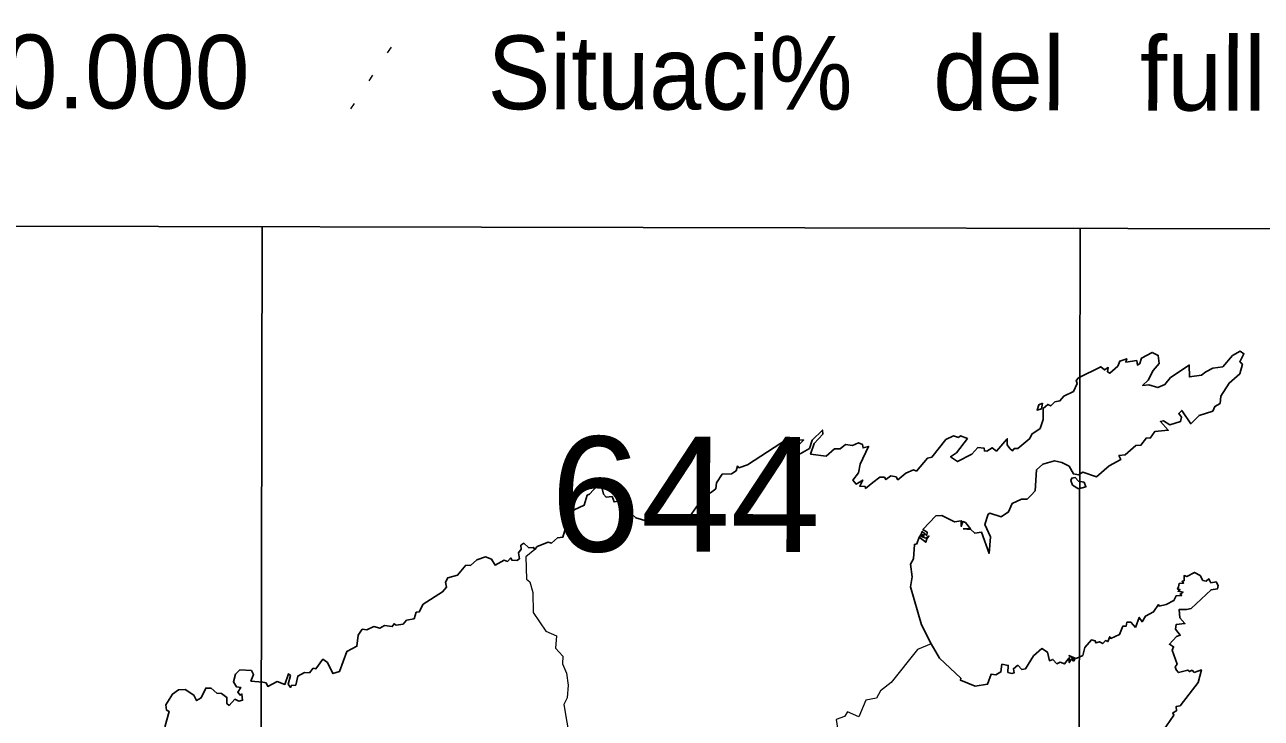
# Model space of a CAD drawing. Extents: x 483843 to 488449, y 4381269 to 4384483.
# Drawn here: x 488069.8 to 488279.3, y 4383527.2 to 4383644.8 of the extents above; entities that cross this region are included whole.
import ezdxf
from ezdxf.enums import TextEntityAlignment as Align

# ---------------------------------------------------------------- set-up
doc = ezdxf.new("R2010")
doc.units = 0
doc.header["$LTSCALE"] = 3.8
doc.linetypes.add('DOTTED', pattern=[1.5, 0.3, -1.2])
for name, color, linetype, lineweight in [('1', 7, 'Continuous', 13), ('2', 7, 'DOTTED', 13), ('3', 7, 'Continuous', 25)]:
    doc.layers.add(name, color=color, linetype=linetype, lineweight=lineweight)

msp = doc.modelspace()

# ---------------------------------------------------------------- linework, layer by layer
at = {"layer": '1', "lineweight": 25}
for p, q in [((487971.5, 4383610.79), (488387.18, 4383609.99)), ((488109.02, 4383068.58), (488110.06, 4383610.53)), ((488247.57, 4383068.31), (488248.62, 4383610.26))]:
    msp.add_line(p, q, dxfattribs=at)
at = {"layer": '2'}
msp.add_line((488125.05, 4383630.5), (488134.4, 4383644.78), dxfattribs=at)
at = {"layer": '3'}
for points in [[(488248.33, 4383584.92), (488252.08, 4383586.8), (488252.73, 4383586.26), (488253.36, 4383586.67), (488253.22, 4383585.97), (488253.64, 4383585.71), (488254.96, 4383586.88), (488255.3, 4383587.73), (488256.49, 4383588.15), (488256.32, 4383587.59), (488258.17, 4383587.86), (488258.29, 4383587.1), (488258.73, 4383587.33), (488259.01, 4383588.27), (488260.77, 4383589.24), (488261.83, 4383588.73), (488261.97, 4383587.35), (488260.97, 4383586.19)], [(488269.87, 4383585.94), (488271.07, 4383586.57), (488272.74, 4383586.78), (488274.41, 4383588.69), (488275.68, 4383589.44), (488276.34, 4383589.02), (488275.62, 4383587.65), (488276.09, 4383587.23), (488275.66, 4383585.62), (488273.81, 4383584.04), (488272.44, 4383581.84), (488272.31, 4383580.58), (488271.42, 4383580.08), (488271.09, 4383579.29)], [(488260.97, 4383586.19), (488260.12, 4383584.51), (488259.16, 4383583.65), (488260.21, 4383583.76), (488261.75, 4383583.26), (488262.96, 4383583.79), (488263.87, 4383584.96), (488267.06, 4383587.08), (488267.11, 4383585.08), (488269.16, 4383585.39), (488269.87, 4383585.94)], [(488248.33, 4383584.92), (488247.9, 4383584.5), (488248.11, 4383583.95), (488247.44, 4383582.61), (488245.82, 4383581.82), (488245.16, 4383581), (488244.33, 4383580.88), (488243.61, 4383580.17), (488243.12, 4383580.42), (488242.33, 4383579.72), (488242.34, 4383577.89), (488241.84, 4383576.35), (488240.41, 4383575.4), (488240.09, 4383574.66), (488238.05, 4383572.95), (488237.44, 4383572.97), (488237.14, 4383572.57), (488236.68, 4383572.96)], [(488271.09, 4383579.29), (488268.73, 4383578.56), (488267.32, 4383577.15), (488265.79, 4383579.41), (488265.29, 4383578.86), (488265.77, 4383578.28), (488265.6, 4383577.5), (488263.76, 4383576.96), (488262.72, 4383577.63), (488262.18, 4383577.52), (488263.51, 4383576.04), (488261.24, 4383575.81), (488260.45, 4383574.72), (488259.81, 4383574.73)], [(488206.98, 4383572.88), (488205.57, 4383571.67), (488202.94, 4383572), (488203.53, 4383573.78), (488205.03, 4383575.38), (488204.93, 4383576.08), (488203.18, 4383574.37), (488202.74, 4383572.95), (488201.17, 4383572.06), (488200.32, 4383572.46), (488200.29, 4383572.94), (488201.74, 4383574.38), (488199.72, 4383574.41)], [(488199.72, 4383574.41), (488199.01, 4383574.59), (488192.23, 4383570.19), (488190.8, 4383569.68), (488190.55, 4383569.97), (488190.3, 4383569.17), (488189.55, 4383568.64), (488187.93, 4383568.57), (488186.98, 4383567.11), (488186.86, 4383566.13), (488186, 4383565.41), (488185.03, 4383565.14)], [(488213.45, 4383567.2), (488212.24, 4383566.18), (488212.16, 4383566.52), (488211.25, 4383566.54), (488211.77, 4383567.6), (488210.63, 4383566.93), (488210.1, 4383567.56), (488211.05, 4383568.83), (488211.31, 4383570.32), (488212.75, 4383573.3), (488211.82, 4383573.05), (488211.73, 4383573.61), (488211.03, 4383573.91), (488210.05, 4383573.47), (488208.87, 4383573.65), (488207.97, 4383572.88), (488206.98, 4383572.88)], [(488228, 4383574.81), (488227.14, 4383575.11), (488225.85, 4383574.5), (488223.48, 4383571.48), (488222.71, 4383571.3), (488220.85, 4383569.12), (488220.39, 4383569.31), (488219.09, 4383568.74), (488217.72, 4383567.64), (488217.42, 4383568.15), (488216.55, 4383568.3), (488215.69, 4383567.69), (488215.43, 4383568.11), (488214.65, 4383568.07), (488213.45, 4383567.2)], [(488236.68, 4383572.96), (488236.23, 4383573.59), (488236.24, 4383574.6), (488234.4, 4383572.51), (488233.68, 4383573.07), (488232.77, 4383572.51), (488232.39, 4383572.54), (488232.34, 4383572.99), (488231.29, 4383573.1), (488230.23, 4383571.99), (488227.79, 4383570.73), (488226.64, 4383571.54), (488227.64, 4383572.19), (488229.5, 4383574.64), (488228.32, 4383575.07), (488228, 4383574.81)], [(488259.81, 4383574.73), (488258.89, 4383573.51), (488258.04, 4383573.45), (488256.23, 4383571.85), (488255.16, 4383571.74), (488255.51, 4383571.1), (488253.51, 4383569.99), (488251.35, 4383568.17), (488249.06, 4383568.96), (488248.32, 4383568.47)], [(488248.32, 4383568.47), (488247.44, 4383568.64), (488246.72, 4383569.94), (488245.49, 4383570.58), (488244.26, 4383570.84), (488242.25, 4383570.32), (488241.21, 4383569.32), (488240.97, 4383565.76), (488240.28, 4383565.06)], [(488248.32, 4383567.43), (488247.74, 4383568.02), (488247.16, 4383567.94), (488247.04, 4383567.53), (488247.3, 4383566.74), (488248.32, 4383566.12)], [(488165.5, 4383565.18), (488166.84, 4383566.66), (488167.61, 4383566.15), (488167.88, 4383565.18)], [(488248.32, 4383567.43), (488249.26, 4383567.24), (488249.57, 4383566.47), (488248.32, 4383566.12)], [(488165.5, 4383565.18), (488165.1, 4383565.02), (488164.6, 4383563.37), (488162.88, 4383562.55), (488161.84, 4383560.78), (488160.96, 4383557.91), (488160.08, 4383557.82), (488159.07, 4383556.93), (488158.47, 4383557.05), (488156.64, 4383556.33), (488156.24, 4383555.85)], [(488167.88, 4383565.18), (488168.3, 4383564.69), (488169.3, 4383564.81), (488169.66, 4383563.89), (488170.72, 4383564.08), (488171.39, 4383563.34), (488172.34, 4383563.58), (488171.94, 4383562.5), (488173.33, 4383561.17), (488175.25, 4383560.63), (488176.34, 4383561.39), (488176.91, 4383561.17), (488177.1, 4383560.55), (488177.52, 4383560.89), (488177.98, 4383560.48), (488179.28, 4383560.83)], [(488185.03, 4383565.14), (488184.83, 4383563.72), (488184.05, 4383563.67), (488181.97, 4383560.75), (488181.15, 4383560.5), (488180.75, 4383560.78), (488180.41, 4383560.33), (488179.28, 4383560.83)], [(488240.28, 4383565.06), (488239.61, 4383564.35), (488238.68, 4383564.37), (488237.06, 4383563.6), (488236.47, 4383562.21), (488235.24, 4383561.34), (488233.29, 4383562), (488232.99, 4383561.8), (488232.43, 4383560.04), (488233.41, 4383557.95), (488233.18, 4383555.16), (488231.9, 4383558.75), (488230.75, 4383558.58), (488230.06, 4383559.2), (488228.75, 4383559.33)], [(488228.75, 4383559.33), (488230.02, 4383559.33), (488229.16, 4383560.42), (488228.74, 4383560.58), (488228.45, 4383559.74), (488228.46, 4383560.71), (488227.3, 4383560.54), (488225.16, 4383561.59), (488224.13, 4383561.52), (488221.96, 4383559.21), (488222.67, 4383558.77), (488222.61, 4383558.23), (488221.85, 4383558.89), (488221.64, 4383558.45), (488222.18, 4383558.26), (488221.54, 4383558.29), (488222.17, 4383557.96), (488221.43, 4383558.13), (488222.47, 4383557.74), (488222.98, 4383558.11), (488222.6, 4383557.63)], [(488222.6, 4383557.63), (488222.44, 4383557.05), (488221.32, 4383557.93), (488220.94, 4383556.8), (488220.53, 4383556.7), (488220.37, 4383554.24), (488219.86, 4383553.35), (488220.16, 4383551.21), (488219.85, 4383549.52), (488221.73, 4383543.04), (488223.37, 4383539.84)], [(488156.24, 4383555.85), (488156, 4383556.17), (488155.22, 4383556.1), (488154.34, 4383556.9), (488153.86, 4383556.54), (488153.93, 4383555.87), (488153.48, 4383555.24), (488153.64, 4383554.26), (488153.17, 4383553.97), (488152.32, 4383554.03), (488152.15, 4383554.4), (488151.61, 4383553.8), (488151.04, 4383554), (488149.48, 4383553.18), (488148.91, 4383554.2), (488147.84, 4383554.56), (488146.39, 4383554.07), (488145.35, 4383553.12), (488144.51, 4383553.2)], [(488144.51, 4383553.2), (488143.13, 4383551.5), (488141.48, 4383551.03), (488141.07, 4383550.31), (488141.25, 4383549.46), (488140.61, 4383548.64), (488137.29, 4383546.54), (488136.64, 4383545.25), (488136.14, 4383545.18), (488135.79, 4383544.06)], [(488265.25, 4383549.52), (488265.38, 4383550.07), (488266.1, 4383550.15), (488265.86, 4383550.46), (488266.21, 4383550.53), (488266.21, 4383551.42), (488266.66, 4383551.24), (488267.96, 4383551.94), (488268.94, 4383551.42), (488269.39, 4383550.6), (488269.96, 4383550.47), (488270.4, 4383550.85), (488270.75, 4383550.19), (488271.61, 4383550.36), (488271.98, 4383549.72), (488271.85, 4383549.15), (488270.78, 4383549.02), (488267.38, 4383545.83), (488266.62, 4383545.65)], [(488257.95, 4383542.59), (488258.59, 4383544.31), (488259.07, 4383543.59), (488259.67, 4383544.53), (488261.02, 4383545.25), (488261.86, 4383546.48), (488261.98, 4383546.23), (488263.15, 4383546.48), (488264.47, 4383547.18), (488264.87, 4383548), (488265.79, 4383548.06), (488265.52, 4383548.28), (488266.04, 4383548.62), (488265.19, 4383548.75), (488265.52, 4383549.06), (488265.1, 4383549.1), (488265.25, 4383549.52)], [(488266.62, 4383545.65), (488265.35, 4383545.64), (488265.47, 4383544.25), (488266.34, 4383543.28), (488264.84, 4383543.1), (488264.77, 4383542.32), (488265.55, 4383541.3), (488264.89, 4383541.07), (488263.7, 4383539.77), (488264.42, 4383539.34), (488264.19, 4383538.79), (488265.01, 4383536.39), (488264.68, 4383535.96), (488264.87, 4383535.43), (488265.28, 4383534.98), (488266.81, 4383535.38), (488267.12, 4383535.13), (488267.54, 4383535.37), (488267.88, 4383534.97)], [(488135.79, 4383544.06), (488134.49, 4383543.86), (488133.9, 4383543.15), (488132.73, 4383542.98), (488132.39, 4383543.25), (488132.06, 4383542.75), (488130.75, 4383542.93), (488129.95, 4383542.49), (488128.96, 4383542.77), (488127.79, 4383542.24), (488126.99, 4383542.32), (488126.28, 4383541.31), (488126.09, 4383539.43), (488124.38, 4383538.56), (488123.15, 4383535.14), (488122.01, 4383534.81), (488121.08, 4383536.68)], [(488248.31, 4383537.53), (488249.04, 4383537.87), (488249.37, 4383539.24), (488250.51, 4383540.51), (488251.15, 4383540.36), (488251.25, 4383540), (488251.86, 4383540.2), (488252.43, 4383539.87), (488252.91, 4383540.4), (488253.3, 4383540.22), (488253.62, 4383541.04), (488253.77, 4383540.75), (488255.27, 4383541.41), (488255.81, 4383542.83), (488256.39, 4383542.85), (488256.51, 4383543.49), (488257.2, 4383543.49), (488257.95, 4383542.59)], [(488223.37, 4383539.84), (488224.77, 4383537.39), (488228.4, 4383534.01), (488228.31, 4383533.66), (488230.79, 4383532.65), (488232.92, 4383532.98), (488233.54, 4383534.72), (488234.33, 4383534.61), (488235.18, 4383535.07), (488235.34, 4383536.39), (488236.42, 4383536.18), (488236.35, 4383535), (488237, 4383534.83), (488237.44, 4383534.95), (488237.29, 4383535.62), (488238.06, 4383536.24)], [(488238.06, 4383536.24), (488238.72, 4383535.48), (488239.35, 4383535.61), (488240.67, 4383537.78), (488242.1, 4383539.03), (488243.04, 4383538.43), (488243.4, 4383536.96), (488243.99, 4383537.2), (488244.67, 4383536.45), (488245.21, 4383536.71), (488245.96, 4383536.44), (488246.75, 4383537.49), (488246.74, 4383536.66), (488247.13, 4383537.27), (488247.49, 4383536.92), (488247.69, 4383537.17), (488246.69, 4383537.86), (488247.89, 4383537.34), (488248.31, 4383537.53)], [(488121.08, 4383536.68), (488120.34, 4383537.22), (488119.15, 4383535.62), (488118.68, 4383535.71), (488118.05, 4383534.95), (488117.23, 4383534.98), (488116.07, 4383534.37), (488115.73, 4383532.86), (488115, 4383532.8), (488114.83, 4383532.44), (488114.47, 4383533.01), (488114.84, 4383534.48), (488114.49, 4383534.75), (488113.9, 4383532.96), (488112.58, 4383533.43), (488110.99, 4383532.61), (488110.69, 4383533.23), (488110.13, 4383533.37)], [(488110.13, 4383533.37), (488108.13, 4383533.53), (488108.59, 4383534.62), (488108.23, 4383535.3), (488106.24, 4383535.42), (488105.51, 4383534.7), (488105.18, 4383533.41), (488105.7, 4383532.55), (488106.41, 4383532.44), (488105.91, 4383531.66), (488106.29, 4383531.14), (488106.62, 4383531.33), (488106.72, 4383530.29), (488106.09, 4383530.12), (488105.43, 4383530.45), (488104.45, 4383529.41), (488104.08, 4383529.7), (488104.06, 4383530.75), (488103.15, 4383531.43), (488102.38, 4383531.47), (488101.41, 4383532.33)], [(488267.88, 4383534.97), (488269.13, 4383535.42), (488268.57, 4383533.26), (488265.52, 4383529.32), (488264.87, 4383529.24), (488264.89, 4383528.5), (488264.29, 4383528.14), (488264.45, 4383527.74), (488262.6, 4383525.01), (488261.46, 4383524.08), (488261.42, 4383523.46), (488260.71, 4383523.62), (488259.98, 4383523.27), (488259.29, 4383522.03), (488257.96, 4383522), (488257.33, 4383521.55), (488256.47, 4383522.17)], [(488101.41, 4383532.33), (488100.47, 4383532.35), (488099.7, 4383530.66), (488098.94, 4383530.23), (488098.49, 4383531.14), (488097.02, 4383532.08), (488095.89, 4383532.03), (488094.84, 4383531.31), (488093.74, 4383529.5), (488093.86, 4383528.6), (488094.31, 4383528.37), (488093.62, 4383525.95), (488093.72, 4383524.91), (488094.56, 4383523.41), (488092.08, 4383523.76), (488091.12, 4383524.85)]]:
    msp.add_lwpolyline(points, dxfattribs=at)
msp.add_lwpolyline([(488242.2, 4383580.63), (488241.58, 4383580.33), (488241.31, 4383579.46), (488242.04, 4383579.67)], close=True, dxfattribs=at)
at = {"layer": '3', "lineweight": 13}
for points in [[(488156.24, 4383555.85), (488154.68, 4383554.57), (488154.83, 4383550.8), (488155.38, 4383550.37), (488155.88, 4383548.56), (488155.93, 4383545.17), (488158.11, 4383541.96), (488159.89, 4383541.21), (488159.75, 4383539.1), (488160.96, 4383537.75), (488160.91, 4383536.44), (488161.6, 4383534.84), (488161.86, 4383532.86), (488161.71, 4383530.69), (488161.12, 4383529.54), (488162.16, 4383523.57), (488162.8, 4383521.82), (488164.05, 4383520.03)], [(488223.37, 4383539.84), (488221.07, 4383538.9), (488216.57, 4383533.28), (488214.77, 4383531.85), (488214.07, 4383530.64), (488212.28, 4383530.27), (488211.1, 4383527.46), (488209.17, 4383528.34), (488208.67, 4383527.5), (488207.25, 4383526.99), (488207.77, 4383523.67), (488207.29, 4383522.17), (488207.84, 4383519.94)]]:
    msp.add_lwpolyline(points, dxfattribs=at)

# ---------------------------------------------------------------- texts
at = {"layer": '2'}
for s, p in [('1:50.000', (488042.84, 4383630.66)), ('del', (488223.68, 4383630.31)), ('full', (488258.69, 4383630.24))]:
    msp.add_text(s, height=12.5, rotation=359.89, dxfattribs=at).set_placement(p)
at = {"layer": '2', "width": 0.95}
msp.add_text('Situaci%', height=12.5, rotation=359.89, dxfattribs=at).set_placement((488148.24, 4383630.46))
at = {"layer": '2', "width": 1.05}
msp.add_text('644', height=19.5, rotation=359.89, dxfattribs=at).set_placement((488181.73, 4383555.46), align=Align.CENTER)

doc.saveas('drawing.dxf')
